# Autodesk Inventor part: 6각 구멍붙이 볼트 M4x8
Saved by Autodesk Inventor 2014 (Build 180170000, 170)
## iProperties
Created: 2026-06
Part Number: 6각 구멍붙이 볼트 M4x8
Material: 강철, 연강
Document SubType Name: Modeling
Designer: dg
Density: 7.86 g/cm^3
Appearance: 강철
Mass: 1.83956 g
Surface Area: 2.80587 cm^2
Volume: 0.234041 cm^3
Author: jhkim
Description: 6각머리 태핑 나사
Creation Date: 2026-05-29
Sending System: Autodesk Inventor 2027
Preprocessor: ST-DEVELOPER v20.1
Author: dg
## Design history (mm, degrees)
node "6각 구멍붙이 볼트 M4x81"
body "Solid1"
node "기준1"
